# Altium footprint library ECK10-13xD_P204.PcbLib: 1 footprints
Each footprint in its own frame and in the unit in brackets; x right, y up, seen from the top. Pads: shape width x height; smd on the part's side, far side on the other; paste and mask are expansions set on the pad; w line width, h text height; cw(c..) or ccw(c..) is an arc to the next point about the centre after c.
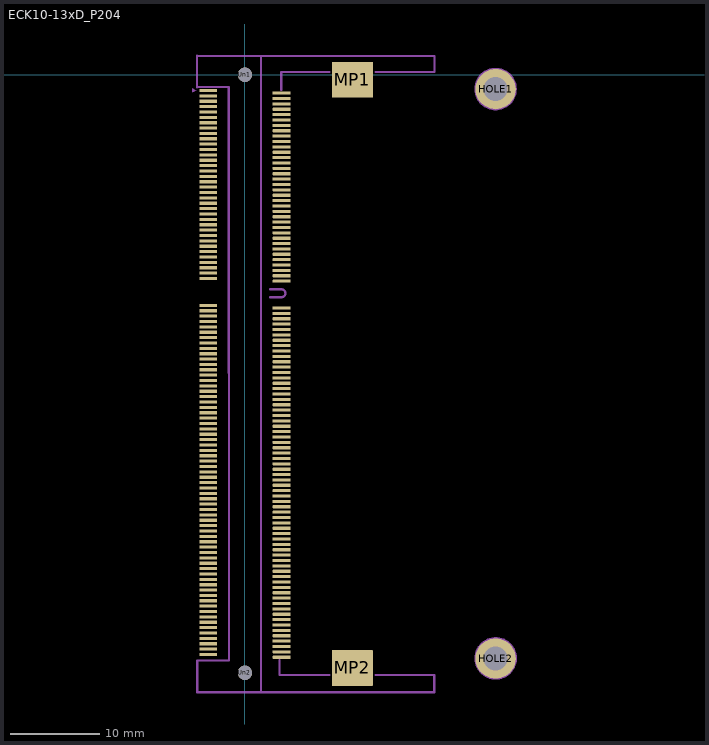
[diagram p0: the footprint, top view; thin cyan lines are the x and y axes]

## ECK10-13xD_P204 [mm]
pads (210):
  rrect25% 2x0.35 smd: 1(-4.1,-1.75) 2(4.1,-2.049) 3(-4.1,-2.35) 4(4.1,-2.65) 5(-4.1,-2.95) 6(4.1,-3.251) 7(-4.1,-3.55) 8(4.1,-3.85) 9(-4.1,-4.15) 10(4.1,-4.449) 11(-4.1,-4.75) 12(4.1,-5.049) 13(-4.1,-5.35) 14(4.1,-5.65) 15(-4.1,-5.95) 16(4.1,-6.25) 17(-4.1,-6.55) 18(4.1,-6.85) 19(-4.1,-7.15) 20(4.1,-7.449) 21(-4.1,-7.75) 22(4.1,-8.05) 23(-4.1,-8.35) 24(4.1,-8.651) 25(-4.1,-8.95) 26(4.1,-9.25) 27(-4.1,-9.55) 28(4.1,-9.85) 29(-4.1,-10.15) 30(4.1,-10.449) 31(-4.1,-10.75) 32(4.1,-11.05) 33(-4.1,-11.35) 34(4.1,-11.65) 35(-4.1,-11.95) 36(4.1,-12.25) 37(-4.1,-12.55) 38(4.1,-12.849) 39(-4.1,-13.15) 40(4.1,-13.45) 41(-4.1,-13.75) 42(4.1,-14.051) 43(-4.1,-14.35) 44(4.1,-14.65) 45(-4.1,-14.95) 46(4.1,-15.25) 47(-4.1,-15.55) 48(4.1,-15.849) 49(-4.1,-16.15) 50(4.1,-16.45) 51(-4.1,-16.75) 52(4.1,-17.05) 53(-4.1,-17.35) 54(4.1,-17.65) 55(-4.1,-17.95) 56(4.1,-18.249) 57(-4.1,-18.55) 58(4.1,-18.85) 59(-4.1,-19.15) 60(4.1,-19.451) 61(-4.1,-19.75) 62(4.1,-20.05) 63(-4.1,-20.35) 64(4.1,-20.65) 65(-4.1,-20.95) 66(4.1,-21.249) 67(-4.1,-21.55) 68(4.1,-21.85) 69(-4.1,-22.15) 70(4.1,-22.45) 71(-4.1,-22.75) 72(4.1,-23.05) 73(-4.1,-25.75) 74(4.1,-26.05) 75(-4.1,-26.35) 76(4.1,-26.649) 77(-4.1,-26.95) 78(4.1,-27.25) 79(-4.1,-27.55) 80(4.1,-27.851) 81(-4.1,-28.15) 82(4.1,-28.45) 83(-4.1,-28.75) 84(4.1,-29.049) 85(-4.1,-29.35) 86(4.1,-29.649) 87(-4.1,-29.95) 88(4.1,-30.251) 89(-4.1,-30.55) 90(4.1,-30.85) 91(-4.1,-31.15) 92(4.1,-31.45) 93(-4.1,-31.75) 94(4.1,-32.049) 95(-4.1,-32.35) 96(4.1,-32.65) 97(-4.1,-32.95) 98(4.1,-33.251) 99(-4.1,-33.55) 100(4.1,-33.85) 101(-4.1,-34.15) 102(4.1,-34.449) 103(-4.1,-34.75) 104(4.1,-35.049) 105(-4.1,-35.35) 106(4.1,-35.65) 107(-4.1,-35.95) 108(4.1,-36.25) 109(-4.1,-36.55) 110(4.1,-36.85) 111(-4.1,-37.15) 112(4.1,-37.449) 113(-4.1,-37.75) 114(4.1,-38.05) 115(-4.1,-38.35) 116(4.1,-38.651) 117(-4.1,-38.95) 118(4.1,-39.25) 119(-4.1,-39.55) 120(4.1,-39.849) 121(-4.1,-40.15) 122(4.1,-40.449) 123(-4.1,-40.75) 124(4.1,-41.05) 125(-4.1,-41.35) 126(4.1,-41.65) 127(-4.1,-41.95) 128(4.1,-42.25) 129(-4.1,-42.55) 130(4.1,-42.849) 131(-4.1,-43.15) 132(4.1,-43.45) 133(-4.1,-43.75) 134(4.1,-44.051) 135(-4.1,-44.35) 136(4.1,-44.65) 137(-4.1,-44.95) 138(4.1,-45.25) 139(-4.1,-45.55) 140(4.1,-45.849) 141(-4.1,-46.15) 142(4.1,-46.45) 143(-4.1,-46.75) 144(4.1,-47.05) 145(-4.1,-47.35) 146(4.1,-47.65) 147(-4.1,-47.95) 148(4.1,-48.249) 149(-4.1,-48.55) 150(4.1,-48.85) 151(-4.1,-49.15) 152(4.1,-49.451) 153(-4.1,-49.75) 154(4.1,-50.05) 155(-4.1,-50.35) 156(4.1,-50.65) 157(-4.1,-50.95) 158(4.1,-51.249) 159(-4.1,-51.55) 160(4.1,-51.85) 161(-4.1,-52.15) 162(4.1,-52.45) 163(-4.1,-52.75) 164(4.1,-53.05) 165(-4.1,-53.35) 166(4.1,-53.649) 167(-4.1,-53.95) 168(4.1,-54.25) 169(-4.1,-54.55) 170(4.1,-54.851) 171(-4.1,-55.15) 172(4.1,-55.45) 173(-4.1,-55.75) 174(4.1,-56.05) 175(-4.1,-56.35) 176(4.1,-56.649) 177(-4.1,-56.95) 178(4.1,-57.25) 179(-4.1,-57.55) 180(4.1,-57.85) 181(-4.1,-58.15) 182(4.1,-58.45) 183(-4.1,-58.75) 184(4.1,-59.049) 185(-4.1,-59.35) 186(4.1,-59.649) 187(-4.1,-59.95) 188(4.1,-60.251) 189(-4.1,-60.55) 190(4.1,-60.85) 191(-4.1,-61.15) 192(4.1,-61.45) 193(-4.1,-61.75) 194(4.1,-62.049) 195(-4.1,-62.35) 196(4.1,-62.65) 197(-4.1,-62.95) 198(4.1,-63.25) 199(-4.1,-63.55) 200(4.1,-63.85) 201(-4.1,-64.15) 202(4.1,-64.449) 203(-4.1,-64.75) 204(4.1,-65.049)
  round 4.5 hole 2.7: HOLE1(28,-1.6) HOLE2(28,-65.2)
  rrect5% 4.6x4 smd: MP1(12,-0.55) MP2(12,-66.25)
  round 1.6 hole 1.6: Un1(0,0) Un2(0,-66.8)
F.SilkS:
  circle w0.254: c28,-1.6 r1.34
  circle w0.254: c28,-1.6 r2.25
  circle w0.254: c28,-65.2 r1.35
  circle w0.254: c28,-65.2 r2.25
  region: -5.443,-1.755 -5.89,-1.95 -5.89,-1.48
  lines w0.254: -5.352,2.089 -5.352,-1.392 -1.796,-1.371 -1.78,-65.402 -5.34,-65.429 -5.34,-68.955 1.82,-68.95 21.14,-68.955 21.14,-67.044 ; -5.352,2.119 1.8,2.1 ; 1.8,-68.8 1.8,2.1 ; 2.84,-25.25 2.84,-24.845 4.075,-24.845 ccw(c4.075,-24.4) 4.075,-23.955 2.84,-23.955 2.84,-23.55 ; 3.861,-65.352 3.861,-67.044 9.449,-67.044 ; 4.044,-1.686 4.044,0.308 9.423,0.308 ; 14.58,-67.031 21.14,-67.031 ; 14.58,0.308 21.18,0.308 21.18,2.057 ; 21.18,2.1 1.8,2.1
F.Fab:
  circle w0.254: c27.991,-1.59 r1.34
  circle w0.254: c27.991,-1.59 r2.25
  circle w0.254: c28.001,-65.176 r1.35
  circle w0.254: c28.001,-65.176 r2.25
  region: -5.443,-1.755 -5.89,-1.95 -5.89,-1.48
  lines w0.254: -5.352,2.089 -5.352,-1.392 -1.796,-1.371 -1.78,-65.402 -5.34,-65.429 -5.34,-68.955 1.82,-68.95 21.14,-68.95 ; -5.352,2.119 1.8,2.1 ; 1.8,-68.8 1.8,2.1 ; 2.84,-24.845 4.075,-24.845 ccw(c4.075,-24.4) 4.075,-23.955 2.84,-23.955 ; 3.861,-65.352 3.861,-67.044 9.449,-67.044 ; 4.041,0.305 9.423,0.305 ; 4.044,-1.686 4.044,0.308 ; 14.58,-67.031 21.14,-67.044 21.14,-68.955 ; 14.58,0.305 21.169,0.305 ; 21.17,2.1 1.8,2.1 ; 21.18,0.308 21.18,2.1
  text "'.Designator'" at 0.951,-36.712 h1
